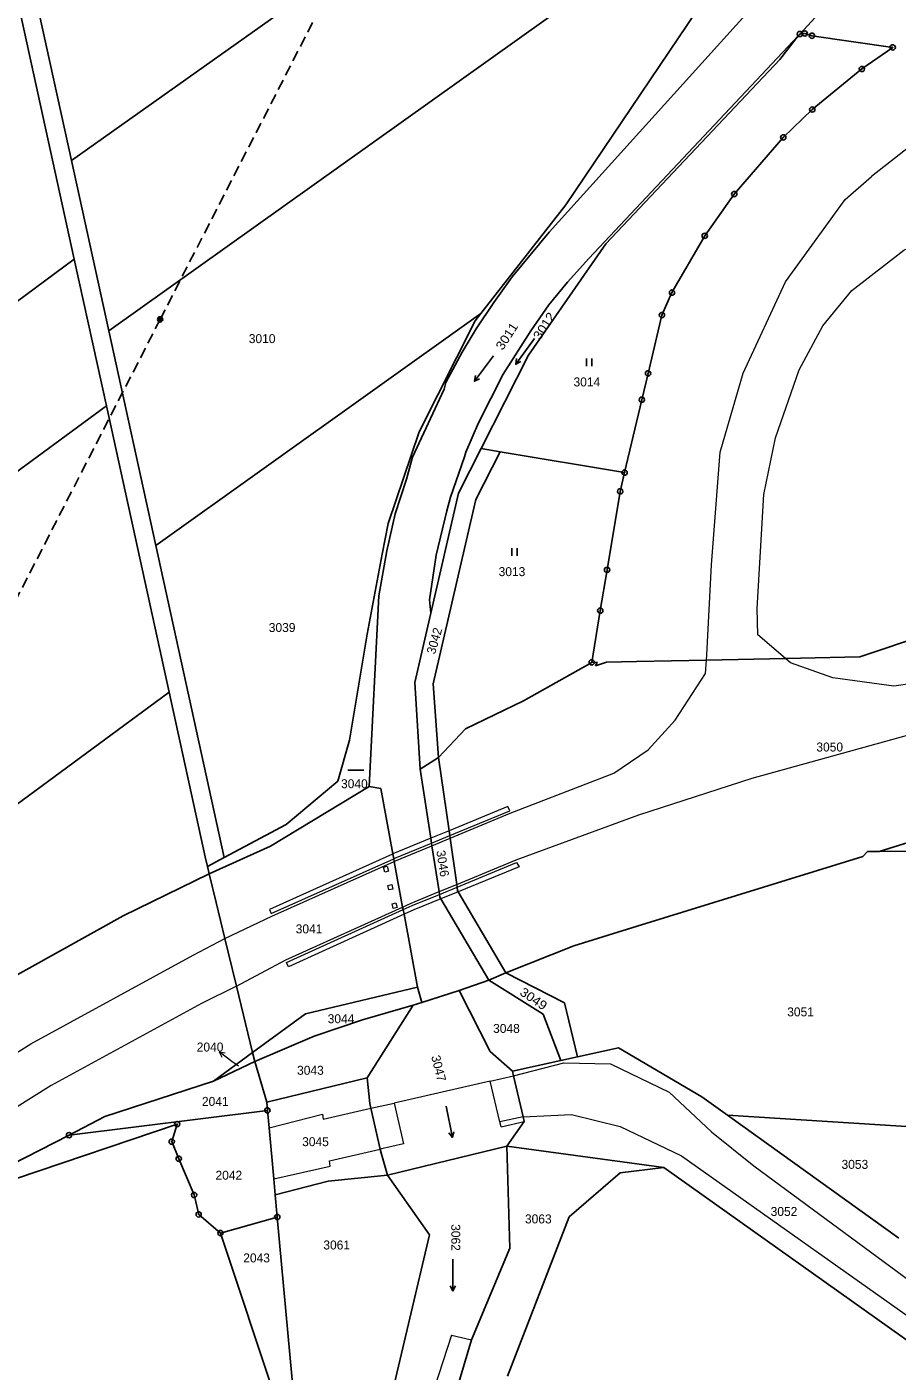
# Model space of a CAD drawing. Extents: x -606517 to -602431, y -1183120 to -1179397.
# Drawn here: x -605135.8 to -604970.9, y -1182528.7 to -1182273.9 of the extents above; entities that cross this region are included whole.
import ezdxf

# ---------------------------------------------------------------- set-up
doc = ezdxf.new("R2010")
doc.units = 0
doc.header["$LTSCALE"] = 0.68
doc.linetypes.add('MEDIUM_DASHED', pattern=[4.5, 3, -1.5])
for name, color, linetype, lineweight in [('1', 7, 'Continuous', 25), ('3', 7, 'Continuous', 25), ('4', 7, 'Continuous', 13), ('6', 7, 'Continuous', 25), ('7', 7, 'Continuous', 13), ('8', 7, 'Continuous', 25)]:
    doc.layers.add(name, color=color, linetype=linetype, lineweight=lineweight)
doc.layers.add('2', color=7, linetype='Continuous')

msp = doc.modelspace()

# ---------------------------------------------------------------- linework, layer by layer
at = {"layer": '1'}
for p, q in [((-605127.38, -1182299.25), (-604973.02, -1182189.69)), ((-605120.31, -1182331.53), (-604990.63, -1182239.03)), ((-605143.37, -1182242.66), (-605126.87, -1182317.96)), ((-604998.82, -1182255.84), (-605033.71, -1182307.66)), ((-605127.38, -1182299.25), (-605134.4, -1182267.21)), ((-604982.4, -1182267.72), (-604989.36, -1182275.27)), ((-604997.9, -1182269.65), (-605036.84, -1182312.8)), ((-604989.7, -1182275.64), (-605029.32, -1182317.83)), ((-604993.15, -1182280.13), (-604989.7, -1182275.64)), ((-604989.7, -1182275.64), (-604989.36, -1182275.27)), ((-604989.36, -1182275.27), (-604988.42, -1182275.17)), ((-604988.42, -1182275.17), (-604987.07, -1182275.6)), ((-604987.07, -1182275.6), (-604971.76, -1182277.81)), ((-604971.76, -1182277.81), (-604977.6, -1182281.9)), ((-605026.11, -1182315.02), (-604993.15, -1182280.13)), ((-604977.6, -1182281.9), (-604987, -1182289.59)), ((-605120.31, -1182331.53), (-605127.38, -1182299.25)), ((-605001.79, -1182305.6), (-605007.38, -1182313.52)), ((-605033.71, -1182307.66), (-605049.8, -1182328.25)), ((-605036.84, -1182312.8), (-605043.88, -1182321.32)), ((-605007.38, -1182313.52), (-605013.59, -1182324.28)), ((-605040.8, -1182336.17), (-605026.11, -1182315.02)), ((-605126.87, -1182317.96), (-605259.98, -1182416.17)), ((-605126.87, -1182317.96), (-605120.78, -1182345.75)), ((-605029.32, -1182317.83), (-605033.38, -1182322.3)), ((-605043.88, -1182321.32), (-605047.38, -1182326.13)), ((-605033.38, -1182322.3), (-605036.9, -1182326.61)), ((-605047.38, -1182326.13), (-605050.67, -1182331.17)), ((-605036.9, -1182326.61), (-605040.35, -1182331.52)), ((-605013.59, -1182324.28), (-605015.5, -1182328.54)), ((-605111.4, -1182372.2), (-605049.8, -1182328.25)), ((-605049.8, -1182328.25), (-605050.9, -1182329.66)), ((-605015.5, -1182328.54), (-605018.12, -1182339.59)), ((-605111.4, -1182372.2), (-605120.31, -1182331.53)), ((-605050.9, -1182329.66), (-605061.51, -1182350.64)), ((-605050.67, -1182331.17), (-605053.35, -1182335.6)), ((-605040.35, -1182331.52), (-605045.61, -1182339.76)), ((-605053.35, -1182335.6), (-605056.46, -1182341.32)), ((-605049.77, -1182353.83), (-605040.8, -1182336.17)), ((-605056.46, -1182341.32), (-605056.74, -1182342.56)), ((-605045.61, -1182339.76), (-605050.26, -1182348.95)), ((-605018.12, -1182339.59), (-605019.3, -1182344.59)), ((-605056.74, -1182342.56), (-605062.79, -1182355.47)), ((-605120.78, -1182345.75), (-605241.79, -1182434.59)), ((-605120.78, -1182345.75), (-605108.9, -1182399.99)), ((-605019.3, -1182344.59), (-605022.57, -1182358.39)), ((-605050.26, -1182348.95), (-605052.64, -1182354.55)), ((-605061.51, -1182350.64), (-605067.36, -1182368.02)), ((-605049.77, -1182353.83), (-605054.06, -1182362.29)), ((-605052.64, -1182354.55), (-605052.91, -1182355.41)), ((-605046.15, -1182354.44), (-605050.75, -1182363.49)), ((-605046.15, -1182354.44), (-605049.77, -1182353.83)), ((-605022.57, -1182358.39), (-605046.15, -1182354.44)), ((-605062.79, -1182355.47), (-605063.88, -1182359.63)), ((-605052.91, -1182355.41), (-605055.55, -1182363.06)), ((-605063.88, -1182359.63), (-605066.02, -1182366.23)), ((-605023.41, -1182361.95), (-605022.57, -1182358.39)), ((-605054.06, -1182362.29), (-605059.31, -1182385.01)), ((-605025.89, -1182376.83), (-605023.41, -1182361.95)), ((-605050.75, -1182363.49), (-605058.83, -1182398.45)), ((-605055.55, -1182363.06), (-605056.28, -1182365.65)), ((-605066.02, -1182366.23), (-605067.63, -1182373.24)), ((-605056.28, -1182365.65), (-605058.31, -1182374.05)), ((-605067.36, -1182368.02), (-605068.52, -1182373.84)), ((-605098.44, -1182431.36), (-605111.4, -1182372.2)), ((-605068.52, -1182373.84), (-605071.35, -1182389)), ((-605067.63, -1182373.24), (-605069.12, -1182381.75)), ((-605058.31, -1182374.05), (-605059.55, -1182382.5)), ((-605027.18, -1182384.55), (-605025.89, -1182376.83)), ((-604978.02, -1182393.33), (-604933.35, -1182378.28)), ((-605069.12, -1182381.75), (-605070.98, -1182417.87)), ((-605059.55, -1182382.5), (-605059.31, -1182385.01)), ((-605059.31, -1182385.01), (-605062.35, -1182398.16)), ((-605028.81, -1182394.36), (-605027.18, -1182384.55)), ((-605071.35, -1182389), (-605074.7, -1182409.12)), ((-605041.72, -1182401.63), (-605028.81, -1182394.36)), ((-605028.81, -1182394.36), (-605027.78, -1182394.34)), ((-605028.1, -1182395), (-605026.03, -1182394.3)), ((-605027.78, -1182394.34), (-605028.1, -1182395)), ((-605026.03, -1182394.3), (-605020.31, -1182394.19)), ((-605020.31, -1182394.19), (-605007.06, -1182393.92)), ((-605007.06, -1182393.92), (-604992.06, -1182393.62)), ((-604992.06, -1182393.62), (-604978.02, -1182393.33)), ((-605108.9, -1182399.99), (-605205.6, -1182471.31)), ((-605108.9, -1182399.99), (-605102.05, -1182431.25)), ((-605062.35, -1182398.16), (-605061.34, -1182414.58)), ((-605058.83, -1182398.45), (-605057.83, -1182412.38)), ((-605052.74, -1182406.96), (-605041.72, -1182401.63)), ((-605057.83, -1182412.38), (-605052.74, -1182406.96)), ((-605074.7, -1182409.12), (-605076.94, -1182416.88)), ((-605061.34, -1182414.58), (-605057.83, -1182412.38)), ((-605055.84, -1182426.28), (-605057.83, -1182412.38)), ((-605059.3, -1182427.71), (-605061.34, -1182414.58)), ((-605070.98, -1182417.87), (-605089.7, -1182429.19)), ((-605076.94, -1182416.88), (-605086.73, -1182425.09)), ((-605068.78, -1182418.24), (-605070.98, -1182417.87)), ((-605066.49, -1182430.67), (-605068.78, -1182418.24)), ((-604974.33, -1182430.2), (-604938.97, -1182419.26)), ((-605086.73, -1182425.09), (-605098.44, -1182431.36)), ((-605059.16, -1182428.61), (-605059.3, -1182427.71)), ((-605055.71, -1182427.18), (-605055.84, -1182426.28)), ((-605055.64, -1182427.69), (-605055.71, -1182427.18)), ((-605054.39, -1182436.45), (-605055.64, -1182427.69)), ((-605089.7, -1182429.19), (-605101.28, -1182434.43)), ((-605066.32, -1182431.58), (-605066.49, -1182430.67)), ((-605059.08, -1182429.12), (-605059.16, -1182428.61)), ((-605057.73, -1182437.82), (-605059.08, -1182429.12)), ((-604976.54, -1182430.21), (-604977.41, -1182431.16)), ((-604974.33, -1182430.2), (-604976.54, -1182430.21)), ((-604963.49, -1182430.17), (-604974.33, -1182430.2)), ((-605102.05, -1182431.25), (-605101.61, -1182433.06)), ((-605101.61, -1182433.06), (-605098.44, -1182431.36)), ((-605101.28, -1182434.43), (-605101.61, -1182433.06)), ((-605066.22, -1182432.1), (-605066.32, -1182431.58)), ((-605064.63, -1182440.73), (-605066.22, -1182432.1)), ((-604977.41, -1182431.16), (-605020.17, -1182444.38)), ((-605101.28, -1182434.43), (-605117.59, -1182442.39)), ((-605101.28, -1182434.43), (-605099.95, -1182439.9)), ((-605057.66, -1182438.33), (-605057.73, -1182437.82)), ((-605057.57, -1182438.88), (-605057.66, -1182438.33)), ((-605054.31, -1182436.95), (-605054.39, -1182436.45)), ((-605054.21, -1182437.68), (-605054.31, -1182436.95)), ((-605054.11, -1182437.85), (-605054.21, -1182437.68)), ((-605045.07, -1182453.22), (-605054.11, -1182437.85)), ((-605099.95, -1182439.9), (-605098.3, -1182446.67)), ((-605064.54, -1182441.23), (-605064.63, -1182440.73)), ((-605064.37, -1182442.11), (-605064.54, -1182441.23)), ((-605057.39, -1182439.19), (-605057.57, -1182438.88)), ((-605048.33, -1182454.59), (-605057.39, -1182439.19)), ((-605117.59, -1182442.39), (-605141.64, -1182455.78)), ((-605061.82, -1182455.94), (-605064.37, -1182442.11)), ((-605020.17, -1182444.38), (-605032.18, -1182448.1)), ((-605098.3, -1182446.67), (-605097.67, -1182449.28)), ((-605032.18, -1182448.1), (-605045.07, -1182453.22)), ((-605097.67, -1182449.28), (-605096.1, -1182455.76)), ((-605045.07, -1182453.22), (-605048.33, -1182454.59)), ((-605033.99, -1182458.87), (-605045.07, -1182453.22)), ((-605096.1, -1182455.76), (-605093.06, -1182468.3)), ((-605061.82, -1182455.94), (-605083.03, -1182460.98)), ((-605061.02, -1182458.85), (-605061.82, -1182455.94)), ((-605053.95, -1182456.55), (-605061.02, -1182458.85)), ((-605053.95, -1182456.55), (-605048.33, -1182454.59)), ((-605048.06, -1182468.09), (-605053.95, -1182456.55)), ((-605048.33, -1182454.59), (-605037.99, -1182461.02)), ((-605062.63, -1182459.32), (-605061.02, -1182458.85)), ((-605031.51, -1182469.1), (-605033.99, -1182458.87)), ((-605083.03, -1182460.98), (-605093.06, -1182468.3)), ((-605062.63, -1182459.32), (-605072.23, -1182462.11)), ((-605071.33, -1182473.08), (-605062.63, -1182459.32)), ((-605037.99, -1182461.02), (-605034.68, -1182469.8)), ((-605072.23, -1182462.11), (-605081.41, -1182465.22)), ((-605081.41, -1182465.22), (-605092.65, -1182469.99)), ((-605093.06, -1182468.3), (-605100.48, -1182473.71)), ((-605093.06, -1182468.3), (-605092.65, -1182469.99)), ((-605043.84, -1182471.81), (-605048.06, -1182468.09)), ((-605034.68, -1182469.8), (-605031.51, -1182469.1)), ((-605031.51, -1182469.1), (-605023.74, -1182467.4)), ((-605023.74, -1182467.4), (-605007.91, -1182476.69)), ((-605092.65, -1182469.99), (-605100.48, -1182473.71)), ((-605092.65, -1182469.99), (-605090.4, -1182477.74)), ((-605034.68, -1182469.8), (-605043.84, -1182471.81)), ((-605043.62, -1182472.73), (-605043.84, -1182471.81)), ((-605100.48, -1182473.71), (-605121.05, -1182480.42)), ((-605090.4, -1182477.74), (-605071.33, -1182473.08)), ((-605070.85, -1182477.96), (-605071.33, -1182473.08)), ((-605041.8, -1182480.47), (-605043.62, -1182472.73)), ((-605007.91, -1182476.69), (-605003.04, -1182480.19)), ((-605090.26, -1182479.27), (-605127.86, -1182483.97)), ((-605090.4, -1182477.74), (-605090.26, -1182479.27)), ((-605090.26, -1182479.27), (-605089.96, -1182482.55)), ((-605070.64, -1182478.88), (-605070.85, -1182477.96)), ((-605068.88, -1182486.63), (-605070.64, -1182478.88)), ((-605107.36, -1182481.88), (-605138, -1182492.25)), ((-605121.05, -1182480.42), (-605127.86, -1182483.97)), ((-605107.36, -1182481.88), (-605108.39, -1182485.2)), ((-605044.88, -1182486.06), (-605041.58, -1182481.39)), ((-605041.58, -1182481.39), (-605041.8, -1182480.47)), ((-605003.04, -1182480.19), (-604963.82, -1182482.7)), ((-604970.59, -1182503.48), (-605003.04, -1182480.19)), ((-605127.86, -1182483.97), (-605155.78, -1182498.2)), ((-605089.96, -1182482.55), (-605089.06, -1182492.27)), ((-605108.39, -1182485.2), (-605107.07, -1182488.44)), ((-605068.67, -1182487.55), (-605068.88, -1182486.63)), ((-605067.48, -1182491.56), (-605044.88, -1182486.06)), ((-605044.88, -1182486.06), (-605044.31, -1182505.36)), ((-605015.15, -1182490.13), (-605044.88, -1182486.06)), ((-605107.07, -1182488.44), (-605104.15, -1182495.31)), ((-605067.48, -1182491.56), (-605068.67, -1182487.55)), ((-605078.77, -1182492.66), (-605067.48, -1182491.56)), ((-605067.48, -1182491.56), (-605059.56, -1182502.87)), ((-605023.39, -1182491.08), (-605033.09, -1182499.42)), ((-605015.15, -1182490.13), (-605023.39, -1182491.08)), ((-604961.46, -1182528.28), (-605015.15, -1182490.13)), ((-605089.06, -1182492.27), (-605088.79, -1182495.25)), ((-605088.79, -1182495.25), (-605078.77, -1182492.66)), ((-605104.15, -1182495.31), (-605103.29, -1182498.99)), ((-605088.79, -1182495.25), (-605088.4, -1182499.49)), ((-605103.29, -1182498.99), (-605099.16, -1182502.53)), ((-605099.16, -1182502.53), (-605088.4, -1182499.49)), ((-605088.4, -1182499.49), (-605083.93, -1182548.26)), ((-605033.09, -1182499.42), (-605044.77, -1182529.64)), ((-605099.16, -1182502.53), (-605083.93, -1182548.26)), ((-605059.56, -1182502.87), (-605075.71, -1182571.55)), ((-605044.31, -1182505.36), (-605051.56, -1182522.76)), ((-605051.56, -1182522.76), (-605067.44, -1182575.26))]:
    msp.add_line(p, q, dxfattribs=at)
msp.add_lwpolyline([(-604987, -1182289.59), (-604992.5, -1182294.87), (-605001.79, -1182305.6)], dxfattribs=at)
at = {"layer": '3'}
for p, q in [((-605043.2, -1182337.846), (-605043.032, -1182336.761)), ((-605029.761, -1182338.24), (-605029.761, -1182336.74)), ((-605028.76, -1182338.24), (-605028.76, -1182336.74)), ((-605051.033, -1182341.074), (-605050.845, -1182339.992)), ((-605043.951, -1182374.19), (-605043.951, -1182372.69)), ((-605042.95, -1182374.19), (-605042.95, -1182372.69)), ((-605075.018, -1182414.78), (-605072.018, -1182414.78)), ((-605055.213, -1182484.383), (-605055.891, -1182483.52)), ((-605055.109, -1182513.487), (-605055.61, -1182512.51))]:
    msp.add_line(p, q, dxfattribs=at)
for points in [[(-605039.674, -1182332.992), (-605043.2, -1182337.846), (-605042.22, -1182337.35)], [(-605047.422, -1182336.283), (-605051.033, -1182341.074), (-605050.044, -1182340.596)], [(-605056.358, -1182478.494), (-605055.213, -1182484.383), (-605054.907, -1182483.328)], [(-605055.109, -1182507.487), (-605055.109, -1182513.487), (-605054.607, -1182512.51)]]:
    msp.add_lwpolyline(points, dxfattribs=at)
at = {"layer": '4'}
for p, q in [((-604951.52, -1182283.15), (-604975.77, -1182302.27)), ((-604997.46, -1182384.17), (-604996.16, -1182362.56)), ((-604997.3, -1182389.14), (-604997.46, -1182384.17)), ((-604968.1, -1182398.34), (-604971.53, -1182398.85)), ((-605044.27, -1182422.97), (-605024.63, -1182415.35)), ((-605055.71, -1182427.18), (-605044.34, -1182422.47)), ((-605055.64, -1182427.69), (-605044.27, -1182422.97)), ((-605044.34, -1182422.47), (-605044.68, -1182421.67)), ((-605059.3, -1182427.71), (-605066.49, -1182430.67)), ((-605066.49, -1182430.67), (-605066.56, -1182430.7)), ((-605089.56, -1182441.99), (-605066.32, -1182431.58)), ((-605066.32, -1182431.58), (-605066.14, -1182431.5)), ((-605054.39, -1182436.45), (-605043.1, -1182431.81)), ((-605054.31, -1182436.95), (-605043.03, -1182432.31)), ((-605043.03, -1182432.31), (-605042.53, -1182433.14)), ((-605062.54, -1182441.28), (-605064.37, -1182442.11)), ((-605057.39, -1182439.19), (-605062.54, -1182441.28)), ((-605098.3, -1182446.67), (-605089.41, -1182442.46)), ((-605064.37, -1182442.11), (-605086.28, -1182452.07)), ((-605104.34, -1182449.88), (-605098.3, -1182446.67)), ((-605135.11, -1182466.69), (-605104.34, -1182449.88)), ((-605096.1, -1182455.76), (-605086.78, -1182450.77)), ((-605086.28, -1182452.07), (-605086.63, -1182451.25)), ((-605096.1, -1182455.76), (-605102.78, -1182459.01)), ((-605102.78, -1182459.01), (-605131.22, -1182474.53)), ((-605169.84, -1182488.45), (-605135.11, -1182466.69)), ((-605048.04, -1182473.74), (-605066.22, -1182477.88)), ((-605048.04, -1182473.74), (-605043.62, -1182472.73)), ((-605131.22, -1182474.53), (-605165.2, -1182495.78)), ((-605070.64, -1182478.88), (-605066.22, -1182477.88)), ((-605089.96, -1182482.55), (-605079.81, -1182479.96)), ((-605041.8, -1182480.47), (-605046.21, -1182481.47)), ((-605045.99, -1182482.39), (-605041.58, -1182481.39)), ((-605078.52, -1182488.86), (-605068.88, -1182486.63)), ((-605078.38, -1182489.84), (-605078.52, -1182488.86)), ((-605011.81, -1182487.88), (-604960.26, -1182524.38)), ((-605089.06, -1182492.27), (-605078.38, -1182489.84)), ((-605055.4, -1182521.86), (-605072.04, -1182573.2)), ((-605055.4, -1182521.86), (-605051.56, -1182522.76))]:
    msp.add_line(p, q, dxfattribs=at)
for points in [[(-605004.48, -1182354.54), (-605000.12, -1182339.53), (-604992.1, -1182322.23), (-604980.76, -1182306.65), (-604975.77, -1182302.27)], [(-604996.16, -1182362.56), (-604993.96, -1182351.8), (-604989.47, -1182338.91), (-604984.99, -1182330.59), (-604979.52, -1182323.91), (-604969.66, -1182316.24), (-604961.18, -1182312.41), (-604951.8, -1182310.7), (-604944.18, -1182310.98), (-604934.38, -1182312.69), (-604924.1, -1182317.34), (-604912.83, -1182327.38), (-604905, -1182340.61), (-604902.55, -1182357.01), (-604903.28, -1182375.38), (-604905.87, -1182384.3)], [(-605007, -1182392.92), (-605006.08, -1182375.85), (-605004.48, -1182354.54)], [(-604991.1, -1182394.44), (-604992.06, -1182393.62), (-604997.3, -1182389.14)], [(-605007.23, -1182396.47), (-605007.06, -1182393.92), (-605007, -1182392.92)], [(-604971.53, -1182398.85), (-604983.11, -1182397.3), (-604991.1, -1182394.44)], [(-605024.63, -1182415.35), (-605018.11, -1182410.91), (-605012.96, -1182405.3), (-605007.23, -1182396.47)], [(-605043.1, -1182431.81), (-605019.87, -1182423.25), (-604998.42, -1182416.34), (-604953.68, -1182403.94), (-604931.53, -1182399.25)], [(-605044.68, -1182421.67), (-605055.84, -1182426.28), (-605059.3, -1182427.71)], [(-605066.14, -1182431.5), (-605059.16, -1182428.61), (-605055.71, -1182427.18)], [(-605065.96, -1182431.98), (-605059.08, -1182429.12), (-605055.64, -1182427.69)], [(-605066.56, -1182430.7), (-605089.85, -1182441.17), (-605089.56, -1182441.99)], [(-605089.41, -1182442.46), (-605066.22, -1182432.1), (-605065.96, -1182431.98)], [(-605042.53, -1182433.14), (-605054.11, -1182437.85), (-605057.39, -1182439.19)], [(-605063.03, -1182440), (-605057.73, -1182437.82), (-605054.39, -1182436.45)], [(-605062.86, -1182440.47), (-605057.66, -1182438.33), (-605054.31, -1182436.95)], [(-605086.78, -1182450.77), (-605064.63, -1182440.73), (-605063.03, -1182440)], [(-605086.63, -1182451.25), (-605064.54, -1182441.23), (-605062.86, -1182440.47)], [(-605043.62, -1182472.73), (-605034.1, -1182470.27), (-605025.27, -1182470.42), (-605014.1, -1182475.83), (-605006.12, -1182483.34), (-604998.06, -1182489.77), (-604957.48, -1182519.72), (-604957.11, -1182519.95)], [(-605045.99, -1182482.39), (-605046.21, -1182481.47), (-605048.04, -1182473.74)], [(-605079.81, -1182479.96), (-605079.67, -1182480.94), (-605070.64, -1182478.88)], [(-605066.22, -1182477.88), (-605064.49, -1182485.63), (-605068.88, -1182486.63)], [(-605041.8, -1182480.47), (-605032.62, -1182480.03), (-605023.44, -1182482.32), (-605011.81, -1182487.88)]]:
    msp.add_lwpolyline(points, dxfattribs=at)
for points in [[(-605067.54, -1182433), (-605067.31, -1182433.92), (-605068.04, -1182434.1), (-605068.27, -1182433.18)], [(-605066.7, -1182436.49), (-605066.52, -1182437.35), (-605067.25, -1182437.5), (-605067.43, -1182436.64)], [(-605066.63, -1182440.1), (-605065.91, -1182439.91), (-605065.69, -1182440.8), (-605066.41, -1182440.99)]]:
    msp.add_lwpolyline(points, close=True, dxfattribs=at)
at = {"layer": '6', "linetype": 'MEDIUM_DASHED'}
msp.add_line((-605110.59, -1182329.36), (-605159.04, -1182423.6), dxfattribs=at)
msp.add_lwpolyline([(-605110.59, -1182329.36), (-605061.79, -1182234.37), (-605014.59, -1182142.85), (-604968.59, -1182052.84), (-604926.3, -1181970.43), (-604825.79, -1181965.35)], dxfattribs=at)
at = {"layer": '6'}
for radius in [0.5, 0.4, 0.3, 0.2, 0.1]:
    msp.add_circle((-605110.5934, -1182329.3599), radius, dxfattribs=at)
at = {"layer": '7'}
msp.add_line((-605099.377, -1182468.174), (-605098.878, -1182469.177), dxfattribs=at)
msp.add_lwpolyline([(-605095.77, -1182470.87), (-605096.98, -1182469.98), (-605099.377, -1182468.174), (-605098.276, -1182468.377)], dxfattribs=at)
at = {"layer": '8'}
for centre, radius in [((-604989.36, -1182275.2699), 0.5), ((-604989.36, -1182275.2699), 0.0303), ((-604988.42, -1182275.1699), 0.5), ((-604988.42, -1182275.1699), 0.0303), ((-604987.07, -1182275.5999), 0.5), ((-604987.07, -1182275.5999), 0.0303), ((-604971.76, -1182277.8099), 0.5), ((-604971.76, -1182277.8099), 0.0303), ((-604977.6, -1182281.8999), 0.5), ((-604977.6, -1182281.8999), 0.0303), ((-604987, -1182289.5899), 0.5), ((-604987, -1182289.5899), 0.0303), ((-604992.5, -1182294.8699), 0.5), ((-604992.5, -1182294.8699), 0.0303), ((-605001.79, -1182305.5999), 0.5), ((-605001.79, -1182305.5999), 0.0303), ((-605007.38, -1182313.5199), 0.5), ((-605007.38, -1182313.5199), 0.0303), ((-605013.59, -1182324.2799), 0.5), ((-605013.59, -1182324.2799), 0.0303), ((-605015.5, -1182328.5399), 0.5), ((-605015.5, -1182328.5399), 0.0303), ((-605018.12, -1182339.5899), 0.5), ((-605018.12, -1182339.5899), 0.0303), ((-605019.3, -1182344.5899), 0.5), ((-605019.3, -1182344.5899), 0.0303), ((-605022.57, -1182358.3899), 0.5), ((-605022.57, -1182358.3899), 0.0303), ((-605023.41, -1182361.9499), 0.5), ((-605023.41, -1182361.9499), 0.0303), ((-605025.89, -1182376.8299), 0.5), ((-605025.89, -1182376.8299), 0.0303), ((-605027.18, -1182384.5499), 0.5), ((-605027.18, -1182384.5499), 0.0303), ((-605028.81, -1182394.3599), 0.5), ((-605028.81, -1182394.3599), 0.0303), ((-605090.26, -1182479.2699), 0.5), ((-605090.26, -1182479.2699), 0.0303), ((-605107.36, -1182481.8799), 0.5), ((-605107.36, -1182481.8799), 0.0303), ((-605127.86, -1182483.9699), 0.5), ((-605127.86, -1182483.9699), 0.0303), ((-605108.39, -1182485.1999), 0.5), ((-605108.39, -1182485.1999), 0.0303), ((-605107.07, -1182488.4399), 0.5), ((-605107.07, -1182488.4399), 0.0303), ((-605104.15, -1182495.3099), 0.5), ((-605104.15, -1182495.3099), 0.0303), ((-605103.29, -1182498.9899), 0.5), ((-605103.29, -1182498.9899), 0.0303), ((-605088.4, -1182499.4899), 0.5), ((-605088.4, -1182499.4899), 0.0303), ((-605099.16, -1182502.5299), 0.5), ((-605099.16, -1182502.5299), 0.0303)]:
    msp.add_circle(centre, radius, dxfattribs=at)

# ---------------------------------------------------------------- texts
at = {"layer": '2', "width": 1.1}
for s, rotation, p in [('3012', 57, (-605038.603, -1182333.391)), ('3011', 57, (-605045.693, -1182335.341)), ('3049', 326, (-605042.597, -1182457.262))]:
    msp.add_text(s, height=1.7, rotation=rotation, dxfattribs=at).set_placement(p)
at = {"layer": '2'}
for s, p in [('3010', (-605093.79, -1182333.855)), ('3014', (-605032.25, -1182342.065)), ('3013', (-605046.44, -1182378.015)), ('3039', (-605090, -1182388.605)), ('3050', (-604986.23, -1182411.255)), ('3040', (-605076.31, -1182418.215)), ('3041', (-605084.9, -1182445.725)), ('3044', (-605078.84, -1182462.755)), ('3051', (-604991.75, -1182461.455)), ('3048', (-605047.49, -1182464.595)), ('2040', (-605103.66, -1182468.115)), ('3043', (-605084.64, -1182472.525)), ('2041', (-605102.67, -1182478.425)), ('3045', (-605083.68, -1182486.055)), ('3053', (-604981.46, -1182490.355)), ('2042', (-605100.1, -1182492.415)), ('3063', (-605041.45, -1182500.695)), ('3052', (-604994.89, -1182499.285)), ('3061', (-605079.66, -1182505.635)), ('2043', (-605094.84, -1182508.085))]:
    msp.add_text(s, height=1.7, dxfattribs=at).set_placement(p)
for s, rotation, p in [('3042', 74, (-605058.501, -1182392.937)), ('3046', 279, (-605058.269, -1182430.116)), ('3047', 284, (-605059.232, -1182469.062)), ('3062', 270, (-605055.415, -1182500.84))]:
    msp.add_text(s, height=1.7, rotation=rotation, dxfattribs=at).set_placement(p)

doc.saveas('drawing.dxf')
